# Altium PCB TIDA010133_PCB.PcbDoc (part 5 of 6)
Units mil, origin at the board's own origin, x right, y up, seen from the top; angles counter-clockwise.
Board outline 4100 x 6400 mil, 8 copper layers (Top Layer, Ground 1, Signal 1, Power 1, Ground 2, Signal 2, Power 2, Bottom Layer), stack 60.4 mil thick; 587 components, 322 nets, 1661 pads, 859 vias.
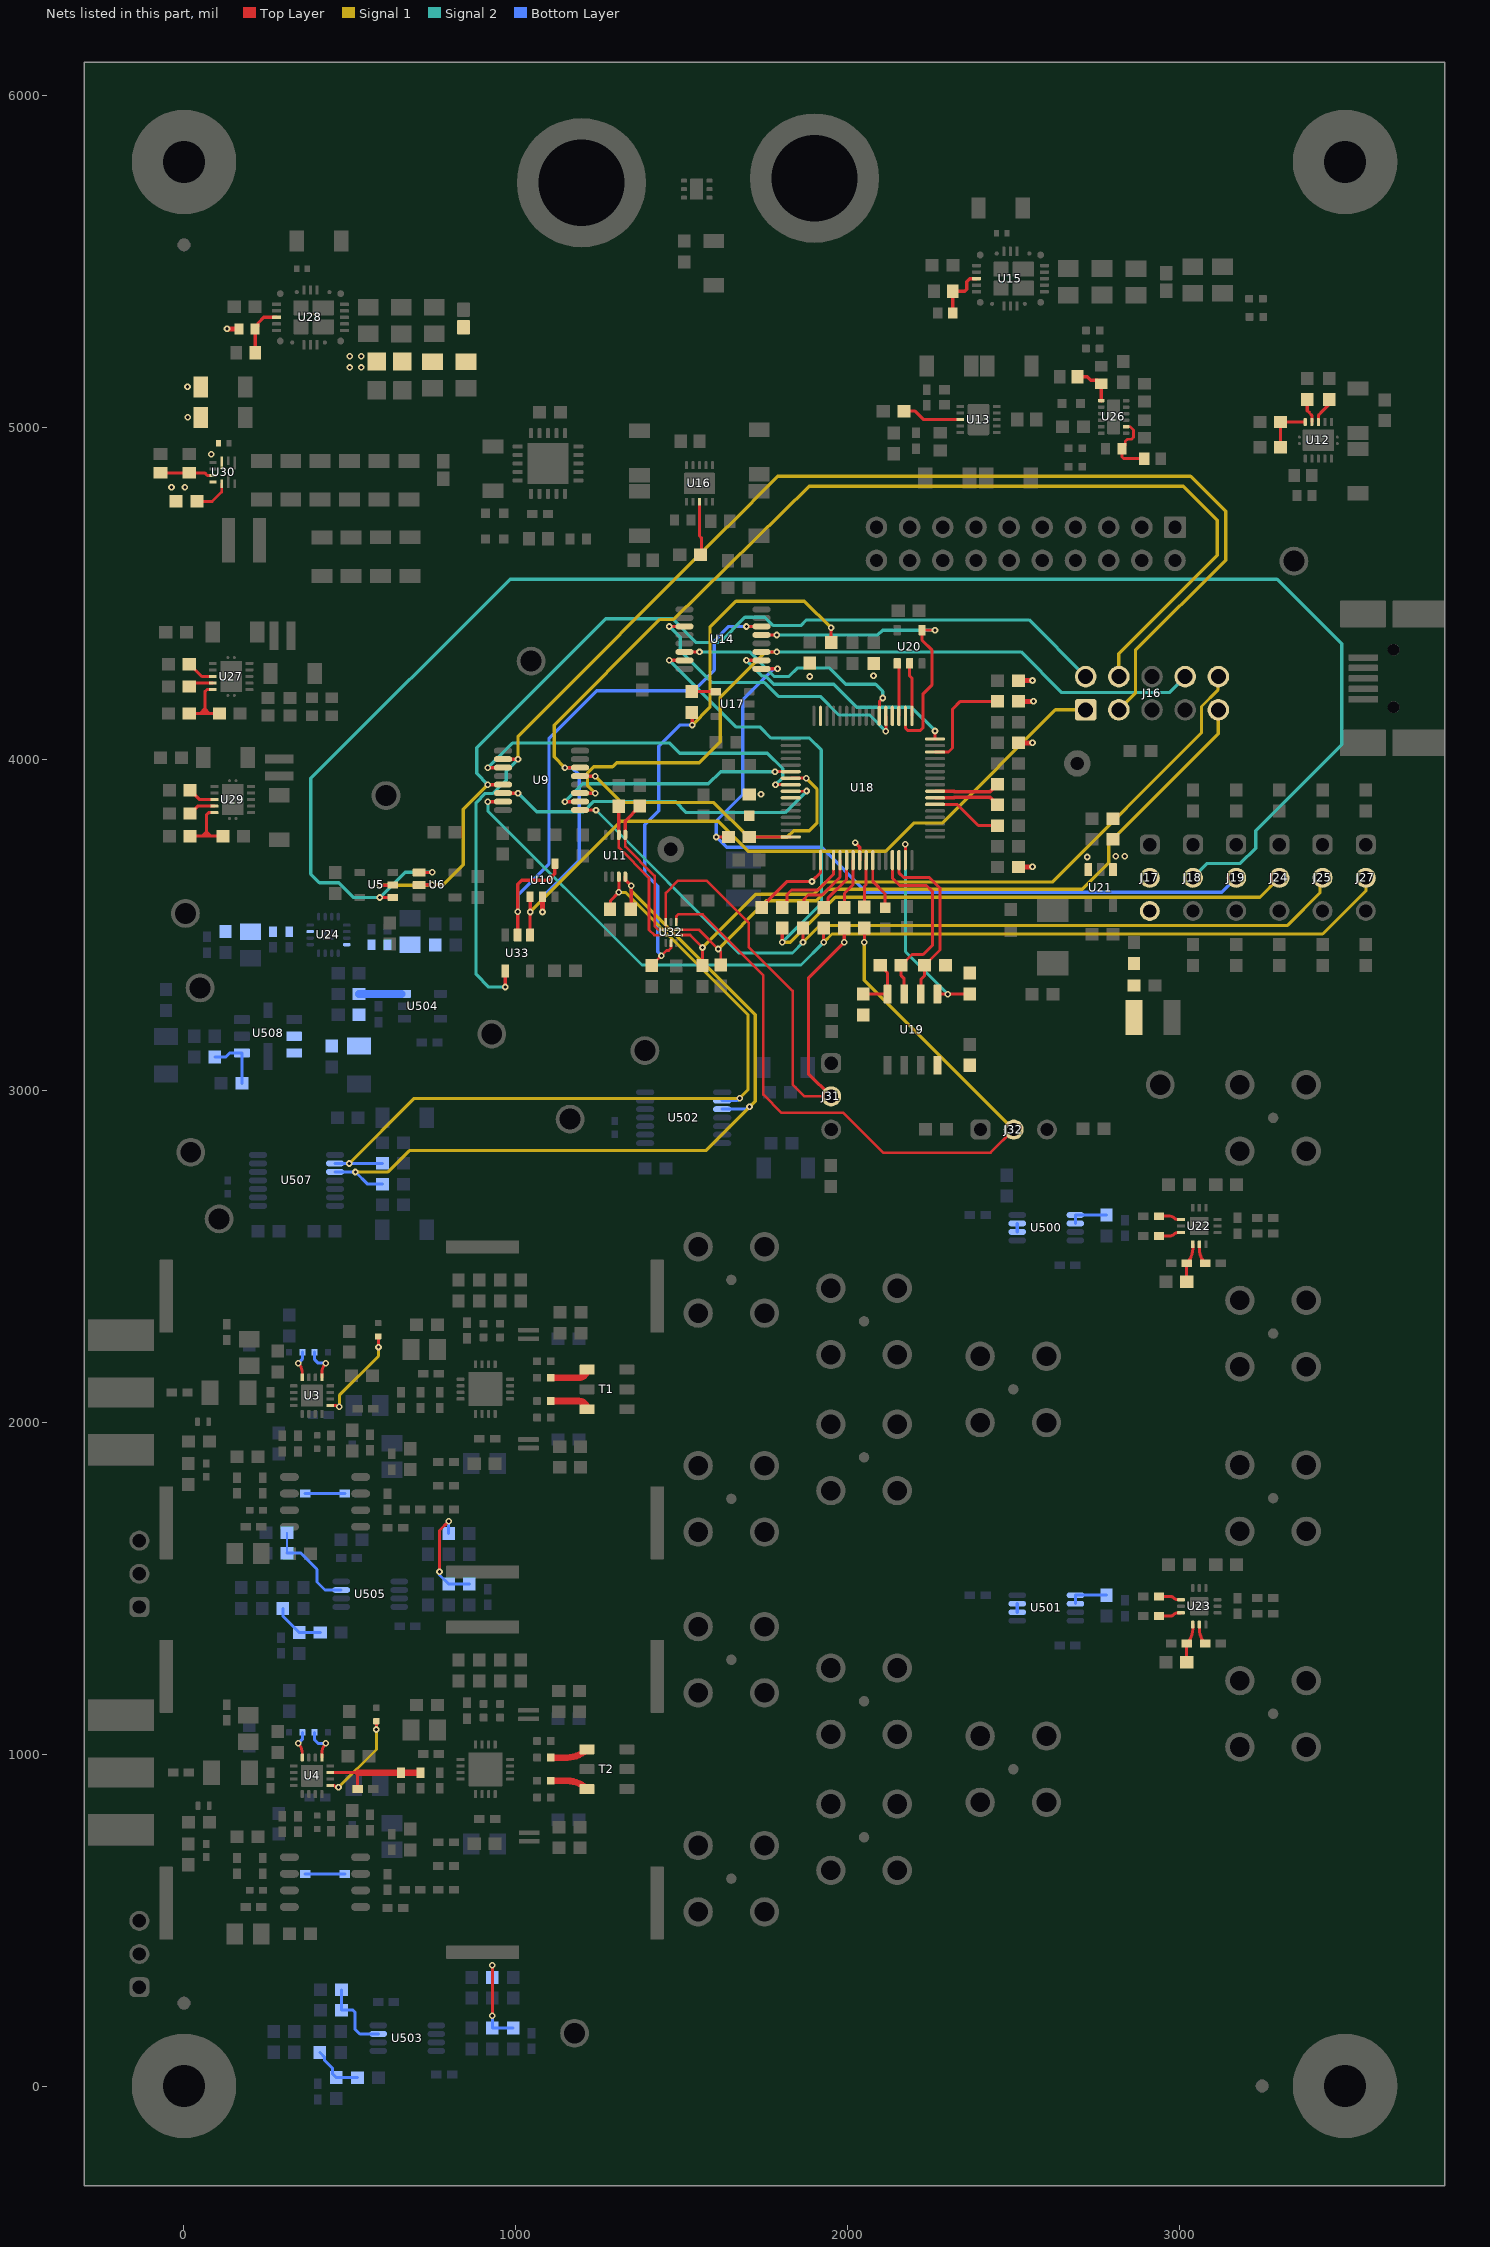
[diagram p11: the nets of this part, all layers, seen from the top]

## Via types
v1: diameter 20, hole 10, Top Layer to Bottom Layer, tented top, 776 vias
v2: diameter 19.68, hole 7.87, Top Layer to Bottom Layer, tented bottom, 82 vias
v3: diameter 19.68, hole 7.87, Top Layer to Bottom Layer, 1 vias

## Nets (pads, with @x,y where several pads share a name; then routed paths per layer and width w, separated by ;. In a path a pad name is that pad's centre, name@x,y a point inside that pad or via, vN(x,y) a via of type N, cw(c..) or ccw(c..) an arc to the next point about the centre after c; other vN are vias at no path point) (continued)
NetR66_1: R66.1 R107.2 R128.2 U32.4 | length 1715.4
  Top Layer w8: R66.1@1410.08,3378.51 v1(1439.23,3407.66) 1454.69,3423.13 1460.81,3423.13 1468.15,3430.47 U32.4@1468.15,3439.13
  Top Layer w10: R66.1@1410.08,3377.53 R66.1@1410.08,3378.51 ; R107.2@1531.18,4140.15 1531.7,4139.63 v1(1531.7,4102.57) ; R128.2@1950.64,4352.16 v1(1950.64,4395.97)
  Signal 1 w10: v1(1531.7,4102.57) 1585.53,4156.41 1585.53,4397.81 1663.84,4476.12 1870.49,4476.12 v1(1950.64,4395.97)
  Bottom Layer w10: v1(1439.23,3407.66) 1428.17,3418.72 1428.17,3617.06 1389.34,3655.89 1389.34,3802.46 1431.41,3844.53 1431.41,4039.3 1494.68,4102.57 v1(1531.7,4102.57)
NetR68_2: R68.2 U12.3 | length 81.7
  Top Layer w9.29: U12.3@3419.63,5016.08 3419.63,5036.41 3426.67,5043.45
  Top Layer w10: 3426.67,5043.45 3453,5069.78 R68.2@3453,5083.98
NetR69_2: R69.2 U12.4 | length 73.7
  Top Layer w9.29: 3392.91,5043.45 3399.95,5036.41 U12.4@3399.95,5016.08
  Top Layer w10: R69.2@3386,5083.98 3386,5050.36 3392.91,5043.45
NetR71_2: R71.2 R76.2 U12.5 | length 150.3
  Top Layer w9: R71.2@3306,4940 R76.2@3306,5016.08 U12.5@3380.26,5016.08
NetR80_1: R80.1 R82.2 U15.22 | length 165.9
  Top Layer w9.84: R82.2@2317.64,5410 2354.04,5410 2359.8,5415.77 2359.8,5439.15 2368.91,5448.25 U15.22@2388.98,5448.25
  Top Layer w10: R80.1@2317.64,5345 R82.2@2317.64,5410
NetR81_1: R81.1 U18.57 | length 143.6
  Top Layer w9: R81.1@2051.26,3554.04 2051.26,3616.75 2056.57,3622.06 U18.57@2056.57,3695.4
NetR90_1: R90.1 R91.2 U26.2 | length 198.5
  Top Layer w8: U26.2@2840.07,5001.78 2852.76,5001.78 2862.42,4992.12 2862.42,4970.42 2856.01,4964.01 2843.47,4964.01 2837.06,4957.6 2837.06,4944.94 R90.1@2827.65,4935.53 2827.65,4911.26 2832.91,4906 R91.2@2895,4906
NetR97_1: R97.1 U13.8 | length 179.5
  Top Layer w9.45: R97.1@2171,5049 2204.19,5049 2229.75,5023.44 U13.8@2339.94,5023.44
NetR98_1: R98.1 R99.2 U26.7 | length 130.8
  Top Layer w9.84: R98.1@2693.48,5152.29 2722.56,5152.29 2733.17,5141.68 2754.36,5141.68 R99.2@2765.19,5130.85 U26.7@2765.19,5080.59
NetR102_2: R102.2 U27.3 | length 86.1
  Top Layer w9.45: R102.2@16.28,4286.54 53.82,4249 U27.3@86.88,4249
NetR104_2: R104.2 U27.4 | length 73
  Top Layer w9.45: R104.2@18.33,4218.63 29.01,4229.31 U27.4@86.88,4229.31
NetR107_1: R107.1 U17.4 | length 72.4
  Top Layer w9: R107.1@1531.18,4203.14 U17.4@1603.62,4203.14
NetR109_2: R109.2 R112.2 U27.5 | length 223.2
  Top Layer w9.45: R109.2@15.74,4137.42 62.84,4137.42 ; 48.68,4137.42 62.84,4151.58 77,4137.42 ; U27.5@86.88,4209.63 69.36,4209.63 62.84,4203.11 62.84,4137.42 ; R112.2@106.41,4137.42 62.84,4137.42
NetR111_2: R111.2 U16.8 | length 162.6
  Top Layer w9.45: U16.8@1554,4775.88 1554,4672.71 1560.45,4666.26 R111.2@1560.45,4616
NetR115_1: R115.1 U18.48 | length 125.2
  Top Layer w9: R115.1@1704.02,3765.28 U18.48@1829.21,3765.28
NetR119_2: R119.2 T1.4 | length 120.6
  Top Layer w20: R119.2@1108.62,2065 1190.16,2065 cw(c1190.16,2040.16) T1.4@1215,2040.16
NetR120_2: R120.2 T1.6 | length 120.6
  Top Layer w20: R120.2@1108.62,2135 1190.16,2135 ccw(c1190.16,2159.84) T1.6@1215,2159.84
NetR123_2: R123.2 T2.4 | length 113
  Top Layer w20: R123.2@1108.62,920 1154.99,920 cw(c1154.99,835.18) T2.4@1214.96,895.16
NetR124_2: R124.2 T2.6 | length 113
  Top Layer w20: R124.2@1108.62,990 1154.99,990 ccw(c1154.99,1074.82) T2.6@1214.96,1014.84
NetR126_1: R126.1 U18.52 | length 257.8
  Top Layer w9: R126.1@1803.55,3558.72 R126.1@1803.55,3553.3 1817.75,3567.5 1817.75,3591.42 1831.47,3605.14 1910.45,3605.14 1958.15,3652.84 U18.52@1958.15,3695.4
NetR127_1: R127.1 U18.53 | length 213.4
  Top Layer w9: R127.1@1865.95,3553.3 1868.93,3556.28 1868.93,3577.71 1881.35,3590.14 1923.88,3590.14 1977.83,3644.09 U18.53@1977.83,3695.4
NetR129_1: R129.1 U18.54 | length 170.8
  Top Layer w9: R129.1@1928.35,3553.3 1940.75,3565.7 1940.75,3580.38 1997.52,3637.15 U18.54@1997.52,3695.4
NetR131_1: R131.1 R133.1 U19.4 | length 169.5
  Top Layer w9: R131.1@2047.19,3291.61 U19.4@2121.09,3291.61 2121.09,3355.8 R133.1@2098.84,3378.05
NetR132_1: R132.1 U18.55 | length 153.1
  Top Layer w9: R132.1@1990.75,3553.3 1990.75,3595.28 2017.2,3621.73 U18.55@2017.2,3695.4
NetR133_2: R133.2 U18.61 U19.3 | length 564.5
  Top Layer w9: U18.61@2135.31,3695.4 2135.31,3641.39 2157.42,3619.29 2238.02,3619.29 2257.08,3600.23 2257.08,3439.48 2228.48,3410.89 2194.68,3410.89 R133.2@2161.84,3378.05 2161.84,3347.27 2171.09,3338.02 U19.3@2171.09,3291.61
NetR135_1: R135.1 U18.62 U19.2 | length 524.1
  Top Layer w9: U18.62@2155,3695.4 2155,3657.78 2169.19,3643.59 2246.12,3643.59 2278.82,3610.89 2278.82,3424.6 R135.1@2232.27,3378.05 2232.27,3346.83 2221.09,3335.65 U19.2@2221.09,3291.61
NetR136_1: R136.1 U18.63 U19.1 | length 650.1
  Top Layer w9: U18.63@2174.68,3695.4 v1(2174.68,3743.33) ; U19.1@2271.09,3291.61 v1(2302.58,3291.61) R136.1@2368.57,3291.61
  Signal 2 w9: v1(2174.68,3743.33) 2174.68,3419.5 v1(2302.58,3291.61)
NetR137_2: R137.2 U18.8 | length 198.1
  Top Layer w9.84: U18.8@2264.25,3903.08 2301.95,3903.08
  Top Layer w11: 2301.95,3903.08 2321.53,3903.08 2322.88,3901.74 2429.73,3901.74 R137.2@2452.43,3924.44
NetR138_2: R138.2 U18.7 | length 198.1
  Top Layer w9.84: U18.7@2264.25,3883.39 2301.95,3883.39
  Top Layer w11: 2301.95,3883.39 2321.53,3883.39 2322.88,3884.74 2429.73,3884.74 R138.2@2452.43,3862.03
NetR139_1: R139.1 U18.6 | length 214.7
  Top Layer w9: U18.6@2264.25,3863.71 2330.55,3863.71 2394.63,3799.63 R139.1@2452.43,3799.63
NetR140_2: R140.2 U18.14 | length 320.1
  Top Layer w9: U18.14@2264.25,4021.19 2304.44,4021.19 2316.43,4033.18 2316.43,4150.35 2340.13,4174.05 R140.2@2452.43,4174.05
NetR143_2: R143.2 U22.6 | length 69
  Top Layer w9: R143.2@2939.24,2562.74 2972.16,2562.74 ccw(c2972.16,2580.11) 2984.44,2567.83 cw(c2996.3,2555.97) 2996.3,2572.74 U22.6@3005.54,2572.74
NetR144_2: R144.2 U22.4 | length 69
  Top Layer w9: R144.2@2939.24,2622.11 2972.16,2622.11 cw(c2972.16,2604.75) 2984.44,2617.03 ccw(c2996.3,2628.89) 2996.3,2612.11 U22.4@3005.54,2612.11
NetR145_2: R145.2 U23.6 | length 69
  Top Layer w9: R145.2@2939.24,1416.49 2972.16,1416.49 ccw(c2972.16,1433.85) 2984.44,1421.57 cw(c2996.3,1409.71) 2996.3,1426.49 U23.6@3005.55,1426.49
NetR146_2: R146.2 U23.4 | length 69
  Top Layer w9: R146.2@2939.24,1475.86 2972.16,1475.86 cw(c2972.16,1458.49) 2984.44,1470.77 ccw(c2996.3,1482.63) 2996.3,1465.86 U23.4@3005.54,1465.86
NetR147_2: R147.2 R149.2 U22.7 | length 118.3
  Top Layer w9: R147.2@3022.77,2423.85 R149.2@3022.77,2480.19 ccw(c2978.8,2524.16) 3040.98,2524.16 U22.7@3040.98,2537.31
NetR148_2: R148.2 R150.2 U23.7 | length 118.3
  Top Layer w9: R148.2@3022.77,1277.59 R150.2@3022.77,1333.94 ccw(c2978.8,1377.91) 3040.98,1377.91 U23.7@3040.98,1391.05
NetR154_1: R154.1 U22.8 | length 61.9
  Top Layer w9: U22.8@3060.66,2537.31 3060.66,2523.66 ccw(c3122.13,2523.66) R154.1@3078.67,2480.19
NetR155_1: R155.1 U23.8 | length 61.9
  Top Layer w9: U23.8@3060.66,1391.05 3060.66,1377.4 ccw(c3122.13,1377.4) R155.1@3078.67,1333.94
NetR168_2: R168.2 U29.3 | length 85
  Top Layer w9.45: R168.2@18.68,3906.4 47.07,3878 U29.3@91.88,3878
NetR169_1: R169.1 R171.2 U28.22 | length 156
  Top Layer w9.84: R171.2@214.5,5225 R169.1@214.5,5297 223.35,5305.86 223.35,5314.72 240.39,5331.75 U28.22@278.94,5331.75
NetR170_2: R170.2 U29.4 | length 82.4
  Top Layer w9.45: R170.2@18.68,3836 40.99,3858.31 U29.4@91.88,3858.31
NetR173_1: R173.1 U30.1 | length 111.3
  Top Layer w7.87: R173.1@39.14,4776.71 85.03,4776.71 113.67,4805.35 U30.1@113.67,4830.24
NetR174_2: R174.2 R176.2 U29.5 | length 227.1
  Top Layer w9.45: R174.2@18.68,3768 67.84,3768 ; 54.43,3768 67.84,3781.4 81.24,3768 ; U29.5@91.88,3838.63 74.36,3838.63 67.84,3832.11 67.84,3768 ; R176.2@117,3768 67.84,3768
NetR175_2: R175.2 R178.2 U30.9 | length 161.3
  Top Layer w9.36: R175.2@-70.89,4862.91 R178.2@16,4862.91 62.3,4862.91 70.36,4854.85 U30.9@87.09,4854.85
NetR180_1: R180.1 U3.9 | length 291
  Top Layer w9: U3.9@441.35,2051.5 460.06,2051.5 464.31,2047.25 v1(468.37,2047.25) ; R180.1@585,2260 586.37,2258.63 v1(586.37,2227.52)
  Signal 1 w9: v1(468.37,2047.25) 468.37,2082.01 586.37,2200 v1(586.37,2227.52)
NetR181_1: R181.1 U4.9 | length 271.7
  Top Layer w9: U4.9@441.35,905.25 453.84,905.25 458.7,900.38 v1(465.76,900.38) ; v1(580,1074.54) R181.1@580,1098.35
  Signal 1 w9: v1(465.76,900.38) 580,1014.62 v1(580,1074.54)
NetR500_1: R500.1 U500.1 U500.2 | length 119.5
  Bottom Layer w9: U500.2@2687.14,2600.11 U500.1@2687.14,2625.7 R500.1@2781.05,2625.7
NetR501_1: R501.1 U501.1 U501.2 | length 119.5
  Bottom Layer w9: U501.2@2687.13,1453.86 U501.1@2687.13,1479.45 R501.1@2781.04,1479.45
NetR502_1: R502.1 R503.2 U505.3 | length 293.4
  Bottom Layer w6: R502.1@309.98,1606.22 309.98,1667.11 R503.2@310.19,1667.32
  Bottom Layer w9: R502.1@309.98,1606.22 352.35,1606.22 401.18,1557.39 401.18,1519.05 424.96,1495.27 U505.3@473.81,1495.27
NetR504_1: R504.1 R505.2 U503.3 | length 233.1
  Bottom Layer w9: R505.2@475.07,290.04 475.07,256.95 474.15,256.02 R504.1@474.15,228.4 509.58,228.4 514.86,223.13 514.86,171.94 529.84,156.96 U503.3@585.63,156.96
NetR518_1: R518.1 R519.2 R520.2 | length 288.7
  Top Layer w9: v1(929.57,211.54) v1(929.57,364.38)
  Bottom Layer w9: v1(929.57,211.54) R519.2@929.57,174.85 R518.1@992.1,174.85 ; R520.2@929.57,327.69 v1(929.57,364.38)
NetR523_1: R523.1 R524.2 R525.2 | length 310.4
  Top Layer w9: v1(770.3,1550.52) 770.3,1674.68 v1(797.74,1702.12)
  Bottom Layer w9: v1(770.3,1550.52) 770.3,1540.6 R524.2@797.74,1513.16 R523.1@860.28,1513.16 ; R525.2@797.74,1666 v1(797.74,1702.12)
NetR529_2: R529.2 R535.1 R538.2 | length 160.4
  Bottom Layer w9: R538.2@409.65,101.08 423.86,86.88 423.86,77.53 448.26,53.12 448.26,36.46 R535.1@459.51,25.21 R529.2@523.43,25.21
NetR530_1: R530.1 R540.2 | length 120.1
  Bottom Layer w9: R540.2@365.05,1785.8 R530.1@485.13,1785.8
NetR531_1: R531.1 R539.2 | length 120.1
  Bottom Layer w9: R539.2@365.05,639.55 R531.1@485.13,639.55
NetR533_1: R533.1 U504.3 | length 127.8
  Bottom Layer w23.62: R533.1@528.03,3291.96 U504.3@655.88,3291.96
NetR534_2: R534.2 R541.1 R547.2 | length 156.1
  Bottom Layer w9: R547.2@297.83,1439.38 297.83,1416.8 R541.1@347.43,1367.21 R534.2@410.81,1367.21
NetR536_1: R536.1 U3.13 | length 106.4
  Top Layer w9: U3.13@415.53,2136.37 415.53,2150.06 cw(c456.58,2150.06) v1(427.55,2179.09)
  Bottom Layer w9: R536.1@393.98,2212.12 393.98,2189.51 404.4,2179.09 v1(427.55,2179.09)
NetR537_1: R537.1 U4.13 | length 106.4
  Top Layer w9: U4.13@415.53,990.12 415.53,1003.8 cw(c456.58,1003.8) v1(427.56,1032.83)
  Bottom Layer w9: R537.1@393.98,1065.87 393.98,1043.26 404.4,1032.83 v1(427.56,1032.83)
NetR543_1: R543.1 U3.16 | length 84
  Top Layer w9: v1(344.45,2179.09) cw(c315.42,2150.06) 356.48,2150.06 U3.16@356.48,2136.37
  Bottom Layer w9: v1(344.45,2179.09) 356.57,2191.2 R543.1@356.57,2212.12
NetR544_1: R544.1 U4.16 | length 84
  Top Layer w9: v1(344.45,1032.83) cw(c315.42,1003.8) 356.48,1003.8 U4.16@356.48,990.12
  Bottom Layer w9: v1(344.45,1032.83) 356.57,1044.95 R544.1@356.57,1065.87
NetR553_2: R553.2 R556.1 U508.1 | length 178.7
  Bottom Layer w9: R556.1@93.15,3101.5 125.43,3101.5 138.42,3114.49 U508.1@174.6,3114.49 R553.2@174.6,3022.59
NetU9_2: U9.2 U18.38 | length 763.8
  Top Layer w9: v1(1781.7,3962.13) U18.38@1829.21,3962.13
  Top Layer w10: v1(1148.34,3871.86) U9.2@1193.85,3871.86
  Signal 2 w10: v1(1148.34,3871.86) 1201.92,3925.44 1581.1,3925.44 1617.79,3962.13 v1(1781.7,3962.13)
NetU9_5: U9.5 U18.39 | length 1003
  Top Layer w9: U18.39@1829.21,3942.45 v1(1875.47,3942.45)
  Top Layer w10: U9.5@1193.85,3948.63 v1(1239.35,3948.63)
  Signal 1 w10: v1(1239.35,3948.63) 1319.05,3868.93 1597.41,3868.93 1701.06,3765.28 1819.07,3765.28 1837.44,3783.65 1885.42,3783.65 1907.94,3806.17 1907.94,3909.98 v1(1875.47,3942.45)
NetU9_11: U9.11 U18.40 | length 1100.8
  Top Layer w9: v1(1782.95,3922.76) U18.40@1829.21,3922.76
  Top Layer w10: v1(916.06,3974.22) U9.11@961.56,3974.22
  Signal 2 w10: v1(916.06,3974.22) 990.24,4048.4 1463.97,4048.4 1494.5,4017.87 1758.49,4017.87 1804.7,3971.66 1804.7,3944.51 v1(1782.95,3922.76)
NetU9_14: U9.14 U18.41 | length 1039
  Top Layer w9: U18.41@1829.21,3903.08 v1@1876.2,3903.08
  Top Layer w10: U9.14@961.56,3897.45 v1(1007.07,3897.45)
  Signal 2 w10: v1(1007.07,3897.45) 1063.07,3841.45 1204.47,3841.45 1235.32,3872.3 1480.46,3872.3 1513.94,3838.81 1811.94,3838.81 v1(1876.81,3903.69)
NetU14_2: U14.2 U18.16 | length 726.6
  Top Layer w9: U18.16@2264.25,4060.56 v1@2264.25,4084.96
  Top Layer w10: v1(1695.46,4297.54) U14.2@1740.97,4297.54
  Signal 2 w10: v1(1695.46,4297.54) 1742.73,4250.27 1753.18,4250.27 1778.27,4225.18 1958.55,4225.18 2027.73,4155.99 2192.88,4155.99 v1(2264.08,4084.79)
NetU14_5: U14.5 U18.18 U20.4 | length 983.2
  Top Layer w9: U18.18@2174.68,4130.44 2174.68,4093.34 2182.49,4085.54 2218.43,4085.54 2228.4,4095.52 2228.4,4197.39 2255.44,4224.43 2255.44,4328.08 2224.88,4358.64 U20.4@2224.88,4388.78 v1(2263.8,4388.78)
  Top Layer w10: U14.5@1740.97,4374.31 v1(1786.47,4374.31)
  Signal 2 w10: v1(1786.47,4374.31) 2070.95,4374.31 2071.07,4374.18 2088.47,4374.18 2088.59,4374.31 2091.42,4374.31 2105.89,4388.78 v1(2263.8,4388.78)
NetU14_11: U14.11 U18.21 | length 900
  Top Layer w9: v1@2115.63,4082.93 v1(2115.63,4084.18) U18.21@2115.63,4130.44
  Top Layer w10: v1(1463.18,4399.9) U14.11@1508.69,4399.9
  Signal 2 w10: v1(1463.18,4399.9) 1495.71,4367.37 1495.71,4326.79 1591.7,4230.79 1750.03,4230.79 1792.03,4188.79 1918.66,4188.79 1974.5,4132.95 2066.86,4132.95 v1(2115.63,4084.18)
NetU14_14: U14.14 U18.22 | length 746
  Top Layer w9: U18.22@2095.94,4130.44 2095.94,4173.74 v1(2106.42,4184.22)
  Top Layer w10: U14.14@1508.69,4323.13 v1(1554.19,4323.13)
  Signal 2 w10: v1(1554.19,4323.13) 1705.35,4323.13 1779.47,4249 1822.89,4249 1848.26,4274.37 1946.13,4274.37 1994.87,4225.64 2084.8,4225.64 2106.42,4204.02 v1(2106.42,4184.22)
NetU18_17: U18.17 U20.2 | length 160.8
  Top Layer w9: U20.2@2187.48,4288.39 2187.48,4250.62 2194.37,4243.73 U18.17@2194.37,4130.44
NetU18_19: U18.19 U20.1 | length 160
  Top Layer w9: U20.1@2150.08,4288.39 2155,4283.46 U18.19@2155,4130.44
NetU500_6: U500.6 U500.7 | length 25.6
  Bottom Layer w10: U500.6@2511.94,2574.52 U500.7@2511.94,2600.11
NetU501_6: U501.6 U501.7 | length 25.6
  Bottom Layer w10: U501.6@2511.94,1428.27 U501.7@2511.94,1453.86
OUT_2: C32.1 R27.2 R37.1 U4.11 | length 320.6
  Top Layer w9: U4.11@441.12,944.84 523.5,944.84 R27.2@523.5,895.59
  Top Layer w20: 523.5,944.84 R37.1@653.88,944.84 C32.1@712.5,944.84
PRG_STS: D6.2 U18.58 | length 159.5
  Top Layer w9: U18.58@2076.26,3695.4 2076.26,3631.73 2076.35,3631.64 2113.77,3593.63 D6.2@2113.77,3551.27
SMB_CLK: R95.1 R528.1 U11.4 U502.10 U507.10 | length 2447
  Top Layer w10: U11.4@1330.44,3645.46 1330.44,3635.62 v1(1348.13,3617.93) 1348.13,3548.86 R95.1@1346.59,3547.31
  Signal 1 w10: v1(516.75,2755.5) 615.16,2755.5 679.57,2819.91 1572.95,2819.91 v1(1704.86,2951.82) 1722.03,2968.99 1722.03,3229.27 1348.43,3602.86 1348.43,3617.63 v1(1348.13,3617.93)
  Bottom Layer w9: U507.10@455.4,2755.5 v1(516.75,2755.5) 553.56,2718.69 R528.1@598.11,2718.69 ; U502.10@1622.39,2944.66 1697.7,2944.66 v1(1704.86,2951.82)
SMB_CLK_1: R96.1 U11.5 U32.1 | length 463.4
  Top Layer w8: U11.5@1330.44,3771.44 1330.44,3736.23 1419.05,3647.61 1419.05,3496.85 1430.6,3485.31 U32.1@1446.5,3485.31
  Top Layer w10: U11.5@1330.44,3771.44 1330.44,3813.4 1374.31,3857.27 R96.1@1374.31,3858.25 R96.1@1363.82,3847.76
SMB_DAT: R93.1 R527.1 U11.3 U502.9 U507.9 | length 2370
  Top Layer w9: R93.1@1284.19,3547.31 1285.55,3548.68 1285.55,3573.19 v1(1310.76,3598.39) U11.3@1310.76,3645.46
  Signal 1 w9: v1(497.8,2781.09) 694.12,2977.41 v1(1674.86,2977.41) 1699.62,3002.17 1699.62,3021.52 1699.69,3021.59 1699.69,3038.57 1699.62,3038.64 1699.62,3229.75 1330.98,3598.39 v1(1310.76,3598.39)
  Bottom Layer w9: U507.9@455.4,2781.09 v1(497.8,2781.09) R527.1@598.18,2781.09 ; U502.9@1622.39,2970.25 1667.7,2970.25 v1(1674.86,2977.41)
SMB_DAT_1: R94.1 U11.6 U32.2 | length 461.3
  Top Layer w8: U11.6@1310.76,3771.44 1310.76,3733.28 1401.87,3642.17 1401.87,3485.21 1417.77,3469.31 U32.2@1446.25,3469.31
  Top Layer w10: U11.6@1310.76,3771.44 R94.1@1310.76,3857.8
TPS62913_IBB_IN: C113.2 C115.1 C116.1 C145.1 C146.1 FB2.2 R113.1 R114.1 R169.2 R173.2 U30.6 U30.10 | length 35.7
  Top Layer w15: v1(129.57,5297) R169.2@165.28,5297
  other v1: -37.48,4819.45 2.78,4819.39 82.1,4919.36 11.01,5030.35 10.59,5122.02 499.67,5180.73 534.67,5180.73 499.67,5214.48 534.67,5214.48
U2A_DAC_EN: J27.2 R129.2 U9.15 | length 3087.6
  Top Layer w9: v1(1928.35,3447.68) R129.2@1928.35,3490.31
  Top Layer w10: v1(916.06,3871.86) U9.15@961.56,3871.86
  Signal 1 w9: v1(1928.35,3447.68) 1953.34,3472.67 3432.7,3472.67 3562.51,3602.48 J27.2@3562.51,3642.21
  Signal 2 w9: v1(916.06,3871.86) 916.06,3843.66 1380.73,3378.99 1859.66,3378.99 v1(1928.35,3447.68)
U2A_DAC_SEL: J25.2 R127.2 U9.1 | length 2576.5
  Top Layer w9: v1(1865.95,3447.68) R127.2@1865.95,3490.31
  Top Layer w10: U9.1@1193.85,3846.27 v1(1241.88,3846.32)
  Signal 1 w9: v1(1865.95,3447.68) 1917.27,3499 3327.01,3499 3424.04,3596.03 3424.04,3633.97 J25.2@3432.28,3642.21
  Signal 2 w9: v1(1241.88,3846.32) 1673.09,3415.11 1834.04,3414.92 1834.04,3415.77 v1(1865.95,3447.68)
U2A_I2C_CLK: J16.9 R55.1 U32.7 | length 2079.1
  Top Layer w8: U32.7@1490.06,3485.56 1552.23,3485.56 v1(1610.27,3427.52) 1618.51,3419.31 R55.1@1618.56,3379.53
  Top Layer w15: R55.1@1618.56,3379.53 R55.1@1618.7,3379.67
  Signal 1 w10: v1(1610.27,3427.52) 1755.47,3572.72 1906.31,3572.72 1941.53,3607.94 2708.44,3607.94 2787.73,3687.22 2787.73,3746.43 3118.16,4076.86 J16.9@3118.16,4148.56
U2A_I2C_DAT: J16.10 R67.1 U32.6 | length 2105.9
  Top Layer w8: U32.6@1489.81,3469.56 1525.71,3469.56 v1(1563.09,3432.18) R67.1@1563.09,3377.9
  Signal 1 w9: 1934.3,3628.99 2617.42,3628.99 3067.58,4079.15 3067.58,4158.76 3116.67,4207.85 3116.67,4247.07 J16.10@3118.16,4248.56
  Signal 1 w10: v1(1563.09,3432.18) 1723.52,3592.6 1897.92,3592.6 1934.3,3628.99
U2A_I2C_EN: J32.2 R81.2 U32.8 | length 2368.6
  Top Layer w8: U32.8@1483.9,3508.93 1483.9,3526.16 1489.76,3532.01 1562.96,3532.01 1746.7,3348.28 1746.7,2988.23 1801.4,2933.53 1987.51,2933.53 2107.57,2813.47 2431.53,2813.47 J32.2@2501.29,2883.22
  Top Layer w10: v1@2051.26,3448.14 R81.2@2051.26,3491.05
  Signal 1 w10: v1(2051.12,3447.99) 2051.12,3333.4 J32.2@2501.29,2883.22
U2A_I2C_SEL: J31.2 R132.2 U32.10 | length 1658.8
  Top Layer w8: U32.10@1452.15,3509.18 1452.15,3596.12 1452.59,3596.56 1488.98,3633.38 1575.8,3633.38 1702.18,3506.99 1702.18,3433.46 1834.93,3300.72 1834.93,3019.31 1870.88,2983.36 J31.2@1951.03,2983.36
  Top Layer w10: J31.2@1951.03,2983.36 1882.44,3051.95 1882.44,3339.37 v1(1990.75,3447.68) R132.2@1990.75,3490.31
U2A_LMH6518_SDIO: U10.4 U14.6 U33.2 | length 1703.2
  Top Layer w10: U33.2@1005.78,3469.47 1005.78,3622.68 1018.19,3635.08 1099.18,3635.08 1118.13,3654.03 U10.4@1118.13,3685.16 ; v1(1695.46,4399.9) U14.6@1740.97,4399.9
  Bottom Layer w10: v1(1005.77,3539.41) 1005.77,3589.4 1100.1,3683.73 1100.1,4061.52 1244.63,4206.05 1536.29,4206.05 1598.68,4268.44 1598.68,4356 1642.58,4399.9 v1(1695.46,4399.9)
U2A_LMH_CSSEL: J18.2 U5.1 U6.1 | length 5179.5
  Top Layer w10: v1@590.66,3582.76 U5.1@629.7,3582.76 ; U6.1@708.84,3658.31 v1@747.88,3658.31
  Signal 2 w10: v1(748.01,3658.44) 666.34,3658.44 v1(590.53,3582.63) 511,3582.63 466.04,3627.58 408.24,3627.58 382.32,3653.51 382.32,3941.85 982.84,4542.37 3295.09,4542.37 3489.78,4347.68 3489.78,4043.83 3230.59,3784.63 3230.59,3731.2 3184.72,3685.33 3084.69,3685.33 J18.2@3041.57,3642.21
U2A_LMH_EN: J24.2 R126.2 U14.15 | length 2866.1
  Top Layer w9.5: v1(1803.55,3447.68) R126.2@1803.55,3490.31
  Top Layer w10: v1(1463.18,4297.54) U14.15@1508.69,4297.54
  Signal 1 w9.5: v1(1803.55,3447.68) 1827.67,3447.68 1963.64,3583.66 3243.48,3583.66 J24.2@3302.04,3642.21
  Signal 2 w9.5: v1(1463.18,4297.54) 1663.55,4097.16 1735.77,4097.16 1769.31,4063.62 1885.35,4063.62 1921.1,4027.88 1921.99,3566.13 v1(1803.55,3447.68)
U2A_LMH_SEL: J19.2 R115.2 U14.1 | length 2329.1
  Top Layer w9: v1(1604.34,3765.28) R115.2@1641.02,3765.28
  Top Layer w10: U14.1@1740.97,4271.95 v1(1789,4272)
  Bottom Layer w10: v1(1789,4272) 1787.09,4270.09 1775.03,4270.09 1684.23,4179.29 1684.23,3893.3 1604.34,3813.4 v1(1604.34,3765.28) 1635.63,3733.99 1922.46,3733.99 2057.36,3599.1 3128.69,3599.1 J19.2@3171.8,3642.21
U2A_SDIO_SEL: J16.1 U10.1 U33.1 | length 2117.4
  Top Layer w10: U33.1@1043.18,3469.47 1043.25,3469.54 1043.25,3539.19 v1(1043.32,3539.26) U10.1@1043.32,3584.77
  Signal 1 w10: v1(1043.32,3539.26) 1316.68,3812.62 1610.07,3812.62 1700.35,3722.33 2114.86,3722.33 2199.65,3807.11 2285.58,3807.11 2627.03,4148.56 J16.1@2718.16,4148.56
U2A_SPI_CS: J16.2 U5.2 U6.2 U9.13 | length 2944.5
  Top Layer w10: v1@590.66,3620.16 U5.2@629.7,3620.16 ; U6.2@708.84,3620.9 v1@747.88,3620.9 ; v1(916.06,3923.04) U9.13@961.56,3923.04
  Signal 1 w10: v1(590.53,3620.03) 747.01,3620.03 v1(748.01,3621.03) 781.35,3621.03 841.5,3681.19 841.5,3848.49 v1(916.06,3923.04)
  Signal 2 w10: v1(916.06,3923.04) 882.2,3956.89 882.2,4034.04 1271.06,4422.9 1473.07,4422.9 1544.66,4351.31 1614.35,4351.31 1691.12,4428.08 1751.36,4428.08 1776.95,4402.49 1859.68,4402.49 1876.55,4419.36 2547.36,4419.36 J16.2@2718.16,4248.56
U2A_SPI_MISO: J16.3 U9.10 U33.4 | length 4215.5
  Top Layer w10: U9.10@961.56,3999.81 v1(1007.07,3999.81) ; v1(968.3,3312.86) v1(968.3,3312.86) 968.34,3361.16 U33.4@968.38,3361.2
  Signal 1 w10: v1(1007.07,3999.81) 1007.07,4069.45 1624.22,4686.6 1624.22,4687.35 1636.52,4699.65 1637.27,4699.65 1790.29,4852.67 3034.31,4852.67 3139.99,4746.98 3139.99,4599.85 2868.16,4328.03 2868.16,4198.56 J16.3@2818.17,4148.56
  Signal 2 w10: v1(968.3,3312.86) 918.43,3312.86 880.4,3350.89 880.4,3868.62 908.19,3896.42 931.5,3896.42 970.98,3935.9 970.98,3963.72 v1(1007.07,3999.81)
U2A_SPI_MOSI: J16.4 U9.6 U10.2 | length 3675
  Top Layer w10: v1(1148.34,3974.22) U9.6@1193.85,3974.22
  Top Layer w15: v1(1080.73,3539.26) U10.2@1080.73,3584.77
  Signal 1 w10: v1(1148.34,3974.22) 1115.89,4006.68 1115.89,4101.99 1434.79,4420.9 1476.66,4420.9 1884.54,4822.39 3012.44,4822.39 3114.85,4719.97 3114.85,4614.36 2818.17,4317.67 J16.4@2818.17,4248.56
  Bottom Layer w10: v1(1080.73,3539.26) 1080.73,3584.4 1191.13,3694.81 1191.13,3952.2 1169.11,3974.22 v1(1148.34,3974.22)
U2A_SPI_SCLK: J16.8 U9.3 U14.3 | length 2263.3
  Top Layer w10: U9.3@1193.85,3897.45 v1(1239.35,3897.45) ; U14.3@1740.97,4323.13 v1(1786.47,4323.13)
  Signal 1 w10: v1(1239.35,3897.45) 1216.35,3920.45 1216.35,3957.89 1235.27,3976.81 1291.96,3976.81 1304.27,3989.13 1553.81,3989.13 1616.76,4052.09 1616.76,4186.31 1753.58,4323.13 v1(1786.47,4323.13)
  Signal 2 w10: v1(1786.47,4323.13) 2523.45,4323.13 2645.96,4200.62 2970.22,4200.62 J16.8@3018.16,4248.56
V3P3V_DAC: C536.1 C543.1 C547.1 L509.2 U24.16
V_BUS: C85.2 C94.1 C95.2 J17.3 L22.2 R131.2 R135.2 R136.2 U19.8
VA2P5V_DACREFEXT1: C548.1 C554.1 R532.2 U508.6 U508.7
VA5V_DAC: C561.1 C565.1 C566.1 L515.2 U24.7
VBUS: C92.1 R141.2 U21.1 U21.3
  other v1: 2722.86,3705.02 2808.73,3706.77 2835.77,3706.77
VREGIN: C66.2 C81.2 C82.2 C83.2 C89.2 D5.1 J17.2 L20.2 L21.1 R140.1 U18.20 U18.31 U18.42 U18.50 U18.56 | length 486.1
  Top Layer w9.84: 1874.76,3631.18 v1(1893.02,3631.18) 1918.78,3656.94 U18.50@1918.78,3695.4 ; v1(2023.19,3748.34) 2036.89,3734.64 U18.56@2036.89,3695.4
  Top Layer w10: C81.2@1741.14,3553.3 1741.14,3554.29 1818.04,3631.18 1874.76,3631.18
  Top Layer w15: L20.2@2515.43,3674.83 v1@2557.41,3674.83 ; L21.1@2515.43,4049.24 v1@2557.41,4049.24 ; C89.2@2515.43,4236.45 v1@2557.41,4236.45 ; R140.1@2518.38,4174.05 v1@2560.36,4174.05
  other v1: 2557.91,3675.34 1739.36,3894.38 2557.91,4049.75 2560.87,4174.55 2557.91,4236.95 1886.34,4248.89 2078.5,4251.02
pads on no net: FID1.1 FID2.1 FID3.1 FID4.1 FID5.1 FID6.1 H1.1 H2.1 H15.1 H16.1 H500.0 H501.0 H502.0 H503.0 J3.1 J4.1 J7.1 J7.3 J7.5 J7.7 J7.9 J7.11 J7.13 J16.7 J26. J26.4 LBL1.0 T1.5 T2.5 U15.4 U15.19 U18.36 U18.60 U19.6 U19.7 U21.4 U24.10 U24.11 U25.7@1545.46,5700.46 U25.7@1545.46,5735.89 U28.4 U28.19 U30.5 U30.8
copper on no net:
  other v1: 1222.29,3441.84

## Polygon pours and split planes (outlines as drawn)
GND on Top Layer "Top Layer-GND" (solid, remove dead copper, pour order 52905): -311.96,6047.55 -311.96,-352.45 3788.04,-352.45 3788.04,6047.55 3784.47,6047.55
-2.5VA on Top Layer "TOP_LAYER_-2.5VA_P52868" (solid, remove dead copper, pour order 52868): 17 vertices, not listed, extent 2199.74,5057.24 2352.57,5225.98
-5VA_OPA140_1 on Top Layer "TOP_LAYER_-5VA_OPA140_1_P52878" (solid, remove dead copper, pour order 52878): 218.35,1541.31 336.48,1541.31 346.31,1551.14 346.32,1699.76 336.33,1709.74 212.07,1709.74 207.64,1705.31 207.64,1552.02
V_BUS on Top Layer "TOP_LAYER_V_BUS_P52904" (solid, remove dead copper, pour order 52904): 55 vertices, not listed, extent 2019.8,2959.22 2980.99,3601.96
+3.8V_IN_TPS7A94 on Top Layer "TOP_LAYER_+3.8V_IN_TPS7A94_P52903" (solid, remove dead copper, pour order 52903): 25 vertices, not listed, extent 3241.03,5003.5 3666.48,5440.08
+3P3VD on Top Layer "TOP_LAYER_+3P3VD_P52901" (solid, remove dead copper, pour order 52901): 17 vertices, not listed, extent 2863.76,3679.36 3617.3,4002.62
+2.5VA on Top Layer "TOP_LAYER_+2.5VA_P52900" (solid, remove dead copper, pour order 52900): 358.99,2605.56 390.84,2573.71 390.84,2478.04 361.63,2448.83 284.64,2448.83 144.17,2448.83 -1,2594 -1,2705 18.21,2724.21 185.56,2724.21 304.21,2605.56
+5VA_LMH6518_2 on Top Layer "TOP_LAYER_+5VA_LMH6518_2_P52897" (solid, remove dead copper, pour order 52897): 30 vertices, not listed, extent 693.28,1015.88 976.59,1352.01
+5VA_LMH6518_1 on Top Layer "TOP_LAYER_+5VA_LMH6518_1_P52896" (solid, remove dead copper, pour order 52896): 30 vertices, not listed, extent 693.28,2162.14 976.59,2498.27
NetC110_1 on Top Layer "TOP_LAYER_NETC110_1_P52894" (solid, remove dead copper, pour order 52894): 856.41,5432.89 866.39,5422.91 866.39,5338.2 855.23,5327.04 464.91,5327.04 456.05,5335.9 388.46,5335.9 385.56,5338.79 385.56,5384.02 396.28,5394.73 396.28,5429.15 400.02,5432.89
NetC106_1 on Top Layer "TOP_LAYER_NETC106_1_P52893" (solid, remove dead copper, pour order 52893): 2566.09,5452.4 2575,5443.5 2971.62,5443.5 2978.42,5450.3 2978.42,5507.01 2971.5,5513.92 2635.93,5513.92 2600.45,5549.4 2509.16,5549.4 2506.33,5546.57 2506.33,5511.25 2495.6,5500.52 2495.6,5455.3 2498.5,5452.4
+3P3VD on Top Layer "TOP_LAYER_+3P3VD_P52889" (solid, remove dead copper, pour order 52889): 27 vertices, not listed, extent 1352.65,4019.27 1629.55,4310.94
+5.5V_IN_TPS7A94 on Top Layer "TOP_LAYER_+5.5V_IN_TPS7A94_P52884" (solid, remove dead copper, pour order 52884): 27 vertices, not listed, extent -83.12,4182.7 112.71,4418.82
CH2_LMH6518_MVCM on Top Layer "TOP_LAYER_CH2_LMH6518_MVCM_P52882" (solid, remove dead copper, pour order 52882): 972.11,930.46 1000.42,930.46 1027.94,902.94 1027.94,854.96 1046.9,836.01 1142.41,836 1157.25,821.17 1157.24,674.15 1155.83,672.73 1084.48,672.73 1003.43,753.78 1003.43,854.19 970.22,887.4 970.22,928.57
+5.5V_IN_TPS7A94 on Top Layer "TOP_LAYER_+5.5V_IN_TPS7A94_P52880" (solid, remove dead copper, pour order 52880): 24 vertices, not listed, extent -79.19,3811.7 104.11,4041.72
-5VA_OPA140_2 on Top Layer "TOP_LAYER_-5VA_OPA140_2_P52879" (solid, remove dead copper, pour order 52879): 218.35,395.06 336.48,395.06 346.31,404.89 346.32,553.5 336.33,563.48 212.07,563.48 207.64,559.05 207.64,405.76
1P8V_USB on Top Layer "TOP_LAYER_1P8V_USB_P52877" (solid, remove dead copper, pour order 52877): 1580.03,3731.48 1585.12,3736.58 1899.27,3736.58 1903.11,3732.74 1903.11,3674.41 1898.99,3670.29 1862.4,3670.29 1651.28,3670.29 1586.29,3670.29 1580.03,3676.55
CH1_LMH6518_AVCM on Top Layer "TOP_LAYER_CH1_LMH6518_AVCM_P52874" (solid, remove dead copper, pour order 52874): 19 vertices, not listed, extent 970.22,2125.16 1157.24,2370.04
CH2_LMH6518_AVCM on Top Layer "TOP_LAYER_CH2_LMH6518_AVCM_P52873" (solid, remove dead copper, pour order 52873): 19 vertices, not listed, extent 970.22,978.91 1157.25,1223.79
CH1_LMH6518_MVCM on Top Layer "TOP_LAYER_CH1_LMH6518_MVCM_P52872" (solid, remove dead copper, pour order 52872): 19 vertices, not listed, extent 970.22,1833.47 1157.24,2076.72
+8VA_BUF802_1 on Top Layer "TOP_LAYER_+8VA_BUF802_1_P52871" (solid, remove dead copper, pour order 52871): 142.2,2194.09 87.84,2194.09 83.33,2189.58 83.33,2132.09 87.63,2127.79 272.9,2127.79 295.34,2105.35 342.01,2105.35 343.85,2107.13 343.85,2132.33 296.31,2179.87 258.03,2179.87 224.88,2213.02 161.12,2213.02
+8VA_BUF802_2 on Top Layer "TOP_LAYER_+8VA_BUF802_2_P52870" (solid, remove dead copper, pour order 52870): 142.2,1047.84 87.84,1047.84 83.33,1043.33 83.33,985.83 87.63,981.54 272.9,981.54 295.34,959.09 342.01,959.09 343.85,960.88 343.85,986.08 296.31,1033.62 258.03,1033.62 224.88,1066.76 161.12,1066.76
3P3USB on Top Layer "TOP_LAYER_3P3USB_P52869" (solid, remove dead copper, pour order 52869): 17 vertices, not listed, extent 2232.41,3918.07 2479.84,4074.56
VBUS on Top Layer "TOP_LAYER_VBUS_P52866" (solid, remove dead copper, pour order 52866): 2785.6,3649.57 2791.39,3643.78 2840.13,3643.78 2848.69,3652.35 2848.69,3880.24 2842.89,3886.03 2783.76,3886.04 2775.49,3877.77 2775.49,3780.3 2785.6,3770.19 2785.6,3719.49
NetC93_1 on Top Layer "TOP_LAYER_NETC93_1_P52865" (solid, remove dead copper, pour order 52865): 2844.2,3583.65 2837.21,3590.64 2771.78,3590.64 2768.45,3587.31 2768.45,3434.79 2776.3,3426.95 2883.21,3426.95 2886.95,3430.69 2886.95,3470.77 2844.2,3513.52
+12VA on Top Layer "TOP_LAYER_+12VA_P52864" (solid, remove dead copper, pour order 52864): 350.03,5494.3 368.75,5513.01 368.75,5614.92 364.57,5619.1 291.45,5619.1 284.43,5612.08 284.43,5461.92 317.32,5429.03 317.32,5399.49 319.33,5397.48 342.78,5397.48 346.75,5401.44 346.75,5463.56 350.03,5466.84
-3.3VA_BUF802_2 on Top Layer "TOP_LAYER_-3.3VA_BUF802_2_P52862" (solid, remove dead copper, pour order 52862): 27 vertices, not listed, extent 328.82,713.07 532.37,893.64
+5VA_OPA140_1 on Top Layer "TOP_LAYER_+5VA_OPA140_1_P52861" (solid, remove dead copper, pour order 52861): 634.47,1815.49 653.38,1796.59 721.83,1796.59 734.07,1808.83 734.07,1867.35 721.08,1880.35 612.05,1880.35 587.12,1855.43 508.88,1855.43 498.03,1844.57 498.02,1821.73 504.26,1815.49
+5VA_OPA140_2 on Top Layer "TOP_LAYER_+5VA_OPA140_2_P52860" (solid, remove dead copper, pour order 52860): 634.47,669.24 653.38,650.34 721.83,650.33 732.96,661.46 732.96,722.21 721.08,734.09 612.05,734.09 587.13,709.17 508.88,709.17 498.03,698.32 498.03,675.48 504.26,669.24
-3.3VA_BUF802_1 on Top Layer "TOP_LAYER_-3.3VA_BUF802_1_P52859" (solid, remove dead copper, pour order 52859): 27 vertices, not listed, extent 328.82,1859.32 532.37,2039.9
+3P3VD_LMH6518_2 on Top Layer "TOP_LAYER_+3P3VD_LMH6518_2_P52858" (solid, remove dead copper, pour order 52858): 935.77,894.54 942.38,894.54 987.65,849.27 987.65,680.8 972.06,665.21 923.09,665.21 917.81,670.49 917.81,817.11 938.87,838.18 938.87,856.19 932.48,862.58 932.48,891.25
+3P3VD_LMH6518_1 on Top Layer "TOP_LAYER_+3P3VD_LMH6518_1_P52857" (solid, remove dead copper, pour order 52857): 935.77,2040.79 942.38,2040.79 987.65,1995.52 987.65,1827.05 972.06,1811.46 923.09,1811.46 917.8,1816.75 917.8,1963.36 938.87,1984.43 938.87,2002.44 932.48,2008.83 932.48,2037.5
+8VA_BUF802_2 on Top Layer "TOP_LAYER_+8VA_BUF802_2_P52854" (solid, remove dead copper, pour order 52854): 17 vertices, not listed, extent 427.55,957.84 597.96,1079.9
+8VA_BUF802_1 on Top Layer "TOP_LAYER_+8VA_BUF802_1_P52853" (solid, remove dead copper, pour order 52853): 17 vertices, not listed, extent 427.55,2104.09 597.96,2226.15
VREGIN on Top Layer "TOP_LAYER_VREGIN_P52852" (solid, remove dead copper, pour order 52852): 2128.41,4100.04 2137.94,4100.04 2142.64,4104.74 2142.64,4255.29 2127.25,4270.67 2127.25,4312.07 2121.02,4318.29 2060.6,4318.29 2057.86,4315.56 2057.86,4252.58 2124.24,4186.2 2124.24,4104.2
VREGIN on Top Layer "TOP_LAYER_VREGIN_P52851" (solid, remove dead copper, pour order 52851): 19 vertices, not listed, extent 1677.91,3803.09 1859.83,3920.37
+5VA on Top Layer "TOP_LAYER_+5VA_P52850" (solid, remove dead copper, pour order 52850): 365.19,4324.22 308.09,4324.22 303.99,4328.31 303.99,4450.31 308.25,4454.57 365.57,4454.57 372.86,4447.28 372.86,4331.88
+5VA on Top Layer "TOP_LAYER_+5VA_P52849" (solid, remove dead copper, pour order 52849): 239.19,4037.77 239.19,3980.67 243.28,3976.57 365.28,3976.57 369.54,3980.83 369.54,4038.15 362.25,4045.44 246.85,4045.44
VREGIN on Top Layer "TOP_LAYER_VREGIN_P52848" (solid, remove dead copper, pour order 52848): 1913.6,4097.51 1923.14,4097.51 1927.83,4102.21 1927.83,4193.5 1912.45,4208.88 1912.45,4309.54 1906.22,4315.77 1866.84,4315.77 1862.28,4311.21 1862.28,4217.65 1909.44,4170.49 1909.44,4101.68
+5VA_TLV3605_2 on Top Layer "TOP_LAYER_+5VA_TLV3605_2_P52846" (solid, remove dead copper, pour order 52846): 3053.67,1486.24 3068.62,1486.24 3071.45,1489.07 3071.44,1618.93 3067.65,1622.73 3002.46,1622.73 2997.92,1618.19 2997.92,1548.17 3000.72,1545.37 3027.57,1545.37 3052.75,1520.18 3052.75,1487.4
+5VA on Top Layer "TOP_LAYER_+5VA_P52845" (solid, remove dead copper, pour order 52845): 632.67,5051.51 624.92,5059.26 624.92,5142.65 631.58,5149.31 691.78,5149.31 696.4,5144.69 696.4,5058 689.92,5051.51
+5VA_TLV3605_1 on Top Layer "TOP_LAYER_+5VA_TLV3605_1_P52841" (solid, remove dead copper, pour order 52841): 17 vertices, not listed, extent 2997.92,2632.5 3069.62,2771.16
+5VA_LMH6518_1 on Top Layer "TOP_LAYER_+5VA_LMH6518_1_P52844" (solid, remove dead copper, pour order 52844): 1177.42,1896.02 1169.56,1888.16 1169.19,1888.16 1169.19,1818.09 1173.89,1813.39 1245.95,1813.39 1250.77,1818.21 1250.77,1889.93 1244.68,1896.02
+5VA_LMH6518_2 on Top Layer "TOP_LAYER_+5VA_LMH6518_2_P52843" (solid, remove dead copper, pour order 52843): 1175.26,748.79 1167.4,740.93 1167.03,740.93 1167.03,670.86 1171.73,666.16 1243.79,666.16 1248.61,670.98 1248.61,742.7 1242.52,748.79
-3.3VA_BUF802_2 on Top Layer "TOP_LAYER_-3.3VA_BUF802_2_P52842" (solid, remove dead copper, pour order 52842): 427.99,934.74 426.35,933.1 426.35,904.08 419.02,896.75 411.5,896.75 410.15,895.4 410.15,864.99 426.11,849.03 478.7,849.03 498.51,868.83 498.51,930.5 494.28,934.74
-3.3VA_BUF802_1 on Top Layer "TOP_LAYER_-3.3VA_BUF802_1_P52840" (solid, remove dead copper, pour order 52840): 427.99,2080.99 426.35,2079.36 426.35,2050.34 419.02,2043 411.49,2043 410.15,2041.65 410.15,2011.25 419.51,2001.89 485.31,2001.89 498.51,2015.09 498.51,2076.76 494.28,2080.99
VBUS on Top Layer "TOP_LAYER_VBUS_P52839" (solid, remove dead copper, pour order 52839): 2737.34,3636.84 2741.6,3641.09 2741.6,3714.16 2736.53,3719.23 2708.65,3719.23 2704.2,3714.78 2704.2,3641 2708.36,3636.84
NetC117_2 on Top Layer "TOP_LAYER_NETC117_2_P52895" (solid, remove dead copper, pour order 52895): 739.96,4866.14 750.79,4876.96 801.95,4876.96 805.8,4880.81 805.8,4940.89 797.26,4949.43 153.91,4949.43 141.41,4936.94 141.41,4876.1 151.38,4866.14
-3.3VA on Top Layer "TOP_LAYER_-3.3VA_P52885" (solid, remove dead copper, pour order 52885): 24 vertices, not listed, extent 1305.69,4570.9 1520,4788.07
+12VA on Top Layer "TOP_LAYER_+12VA_P52875" (solid, remove dead copper, pour order 52875): 18 vertices, not listed, extent 1587.56,4872.41 1797.02,5027.12
+8VA on Top Layer "TOP_LAYER_+8VA_P52891" (solid, remove dead copper, pour order 52891): 18 vertices, not listed, extent 1588.76,4573.83 1802.49,4787.74
+12VA on Top Layer "TOP_LAYER_+12VA_P52881" (solid, remove dead copper, pour order 52881): 1503.16,5767.43 1515.72,5754.88 1515.72,5649.53 1545.82,5619.42 1627.29,5619.42 1635.34,5611.36 1635.34,5542.28 1629.52,5536.46 1460.64,5536.46 1448.9,5548.2 1448.9,5759.61 1456.72,5767.43
+2.5VA on Top Layer "TOP_LAYER_+2.5VA_P52883" (solid, remove dead copper, pour order 52883): 2351.55,4988.67 2352.54,4987.69 2352.54,4907.85 2328.74,4884.05 2328.74,4791.1 2318.68,4781.04 2197.83,4781.04 2190.1,4788.76 2190.1,4948.74 2195.32,4953.95 2308.32,4953.95 2323.88,4969.51 2323.88,4983.81 2328.74,4988.67
NetC122_2 on Top Layer "TOP_LAYER_NETC122_2_P52855" (solid, remove dead copper, pour order 52855): 23 vertices, not listed, extent 2746.22,5075.06 2858.05,5309.32
-3V_INN_TPS7A39 on Top Layer "TOP_LAYER_-3V_INN_TPS7A39_P52888" (solid, remove dead copper, pour order 52888): 2729.7,5252.79 2731.89,5250.6 2731.89,5205.43 2726.5,5200.05 2618.42,5200.05 2581.62,5163.25 2581.62,5078.97 2560.6,5057.95 2446.3,5057.95 2438.08,5066.18 2438.08,5097.71 2496.81,5156.45 2496.81,5246.47 2503.13,5252.79
+3V_INP_TPS7A39 on Top Layer "TOP_LAYER_+3V_INP_TPS7A39_P52892" (solid, remove dead copper, pour order 52892): 2475.27,4987.91 2565.29,4897.89 2677.35,4897.89 2679.9,4895.35 2679.9,4778.62 2672.11,4770.83 2477.14,4770.83 2467.61,4780.37 2467.61,4909.25 2438.18,4938.68 2438.18,5006.39 2440.48,5008.69 2470.49,5008.69 2475.27,5003.91
NetC121_1 on Top Layer "TOP_LAYER_NETC121_1_P52856" (solid, remove dead copper, pour order 52856): 23 vertices, not listed, extent 2686.31,4858.59 2795.91,5023.01
+3P3VD on Top Layer "TOP_LAYER_+3P3VD_P52867" (solid, remove dead copper, pour order 52867): 17 vertices, not listed, extent 3414.73,4769.51 3587.97,4918.43
LM27762_IN on Top Layer "TOP_LAYER_LM27762_IN_P52890" (solid, remove dead copper, pour order 52890): 2948.61,5427.77 2943.21,5422.36 2943.21,5322.95 2951.93,5314.23 3219.78,5314.23 3226.02,5320.47 3226.02,5425.83 3217.56,5434.29 2998.61,5434.29 2992.09,5427.77
+12VA on Top Layer "TOP_LAYER_+12VA_P52863" (solid, remove dead copper, pour order 52863): 2342.6,5626.13 2354.48,5614.25 2382.31,5614.25 2407.63,5588.93 2407.63,5561.1 2427.36,5541.37 2427.36,5519.12 2432.29,5516.15 2456.79,5516.15 2459.33,5518.69 2459.33,5689 2448.02,5700.31 2351.2,5700.31 2342.6,5691.7
-5.5V_IN_TPS7A33 on Top Layer "TOP_LAYER_-5.5V_IN_TPS7A33_P52899" (solid, remove dead copper, pour order 52899): 27 vertices, not listed, extent 376.6,4644.2 1055.28,5011.65
-5VA on Top Layer "TOP_LAYER_-5VA_P52876" (solid, remove dead copper, pour order 52876): 20 vertices, not listed, extent 942.58,4632.47 1068.12,4846.72
TPS62913_IBB_IN on Top Layer "TOP_LAYER_TPS62913_IBB_IN_P52847" (solid, remove dead copper, pour order 52847): 63.85,4832.22 71.72,4840.1 97.73,4840.1 98.64,4839.19 98.64,4814.09 89.96,4805.41 9.45,4805.41 1.8,4797.75 1.8,4750.34 -7.82,4740.72 -46.26,4740.72 -53.54,4748.01 -53.54,4824.56 -45.87,4832.22
TPS62913_IBB_IN on Top Layer "TOP_LAYER_TPS62913_IBB_IN_P52886" (solid, remove dead copper, pour order 52886): 17 vertices, not listed, extent -13.61,4870.85 117.62,5159.15
TPS62913_IBB_IN on Top Layer "TOP_LAYER_TPS62913_IBB_IN_P52887" (solid, remove dead copper, pour order 52887): 814.15,5226.19 490.67,5226.19 484.42,5219.94 484.42,5176.22 492.05,5168.58 882.35,5168.58 882.36,5168.59 887.35,5173.58 887.35,5313.69 884.15,5316.89 829.45,5316.89 826.26,5313.69 826.26,5238.3
NetC123_1 on Top Layer "TOP_LAYER_NETC123_1_P52902" (solid, remove dead copper, pour order 52902): 29 vertices, not listed, extent -234.99,4093.09 288.21,4530.7
NetC134_1 on Top Layer "TOP_LAYER_NETC134_1_P52898" (solid, remove dead copper, pour order 52898): 26 vertices, not listed, extent -78.44,3625.29 389.58,3961.5
+3P3VD_LMH6518_1 on Bottom Layer "BOTTOM_LAYER_+3P3VD_LMH6518_1_P52955" (solid, remove dead copper, pour order 52955): 924.54,1805.22 977.71,1805.22 986.65,1814.16 986.65,1956.44 977.4,1965.69 934.44,1965.69 915.32,1946.57 915.32,1814.43
GND on Bottom Layer "Top Layer-GND" (solid, remove dead copper, pour order 52980): -300,6100 -300,-300 3800,-300 3800,6100 3796.44,6100
+2.5VA_1 on Bottom Layer "BOTTOM_LAYER_+2.5VA_1_P52962" (solid, remove dead copper, pour order 52962): 634.48,2800.81 634.48,2694.29 643.43,2685.34 747.87,2685.34 765.04,2702.52 765.04,2779.53 734,2810.57 644.25,2810.57
-2.5VA on Bottom Layer "BOTTOM_LAYER_-2.5VA_P52978" (solid, remove dead copper, pour order 52978): 207.18,2932.25 243.49,2968.56 480.1,2968.56 483.07,2965.59 483.07,2895.12 478.59,2890.65 422.42,2890.65 387.05,2855.27 216.3,2855.27 55.86,2694.82 -131.09,2694.82 -153.47,2717.76 -153.47,2913.37 -134.59,2932.25
+3P3VD on Bottom Layer "BOTTOM_LAYER_+3P3VD_P52979" (solid, remove dead copper, pour order 52979): 44 vertices, not listed, extent 385.48,1747.74 1984.5,3853.31
+8VA_BUF802_2 on Bottom Layer "BOTTOM_LAYER_+8VA_BUF802_2_P52977" (solid, remove dead copper, pour order 52977): 25 vertices, not listed, extent 66.14,947.37 604.65,1237.28
+2.5VA_1 on Bottom Layer "BOTTOM_LAYER_+2.5VA_1_P52973" (solid, remove dead copper, pour order 52973): 520.05,2685.74 610.62,2685.74 622.55,2673.81 622.55,2636.53 630.97,2628.1 630.97,2522.85 614.58,2507.19 437.68,2507.19 423.24,2521.63 423.24,2655.26 427.62,2659.64 493.95,2659.64
+5VA on Bottom Layer "BOTTOM_LAYER_+5VA_P52976" (solid, remove dead copper, pour order 52976): -65.62,3438.34 147.46,3438.34 155.95,3429.85 155.95,3249.53 134.64,3228.22 2.36,3228.22 -9.17,3239.75 -9.17,3259.18 -29.17,3279.19 -69.77,3279.19 -82.79,3292.2 -82.79,3421.17
-3.3VA_BUF802_1 on Bottom Layer "BOTTOM_LAYER_-3.3VA_BUF802_1_P52975" (solid, remove dead copper, pour order 52975): 25 vertices, not listed, extent 327.43,1842.97 616.93,2298.49
GND on Bottom Layer "BOTTOM_LAYER_GND_P52974" (solid, remove dead copper, pour order 52974): 409.12,3084.29 417.63,3092.8 577.07,3092.8 603.22,3066.66 603.22,2987.41 599.43,2983.63 285.81,2983.63 236.72,3032.71 236.72,3144.8 240.11,3148.19 266.99,3148.19 274.3,3140.88 274.3,3101.76 291.78,3084.29
+2.5VA_1 on Bottom Layer "BOTTOM_LAYER_+2.5VA_1_P52972" (solid, remove dead copper, pour order 52972): 1699.71,2858.49 1666.25,2858.49 1660.17,2864.13 1650.21,2874.53 1592.2,2874.53 1585.78,2868.11 1585.78,2749.59 1612.6,2722.76 1787.22,2722.76 1794.06,2729.6 1794.06,2893.92 1781.19,2906.79 1748.01,2906.79
-2.5VA_1 on Bottom Layer "BOTTOM_LAYER_-2.5VA_1_P52971" (solid, remove dead copper, pour order 52971): 1579.68,3097.6 1579.68,2994.23 1584.71,2989.2 1658.78,2989.2 1667.08,2997.51 1700.21,2997.51 1726.41,2971.31 1726.41,2945.83 1731.72,2940.53 1786.85,2940.53 1789.48,2943.16 1789.48,3105.89 1782.28,3113.09 1595.18,3113.09
-2.5VA_1 on Bottom Layer "BOTTOM_LAYER_-2.5VA_1_P52970" (solid, remove dead copper, pour order 52970): 19 vertices, not listed, extent 427.96,2800.04 644.56,2967.75
-3.3VA_BUF802_2 on Bottom Layer "BOTTOM_LAYER_-3.3VA_BUF802_2_P52969" (solid, remove dead copper, pour order 52969): 22 vertices, not listed, extent 327.43,696.72 546.64,942.97
VA2P5V_DACREFEXT1 on Bottom Layer "BOTTOM_LAYER_VA2P5V_DACREFEXT1_P52968" (solid, remove dead copper, pour order 52968): 19 vertices, not listed, extent 300.78,3099.42 570.45,3253.24
VA5V_DAC on Bottom Layer "BOTTOM_LAYER_VA5V_DAC_P52967" (solid, remove dead copper, pour order 52967): 94.66,3530.07 94.66,3459.47 99.73,3454.4 241.93,3454.4 245.94,3458.41 340.17,3458.41 356.91,3475.15 392.21,3475.15 393.62,3476.55 393.62,3483.09 391.95,3484.76 357.84,3484.76 305,3537.6 102.19,3537.6
+5VA_REF7025_1 on Bottom Layer "BOTTOM_LAYER_+5VA_REF7025_1_P52966" (solid, remove dead copper, pour order 52966): -24.28,3251.78 -24.28,3203.67 -7.76,3187.15 196.01,3187.15 202.51,3180.65 202.51,3149.12 195.83,3142.44 -1,3142.44 -13.68,3129.77 -87.17,3129.77 -92.34,3134.83 -92.34,3243.03 -72.98,3262.39 -34.89,3262.39
+5VA_C on Bottom Layer "BOTTOM_LAYER_+5VA_C_P52965" (solid, remove dead copper, pour order 52965): 2466.18,1465.21 2473.78,1472.81 2539.73,1472.81 2542.37,1475.44 2542.37,1549.93 2530.82,1561.47 2455.37,1561.47 2449.43,1567.41 2449.43,1633.42 2440.44,1642.41 2401.33,1642.41 2395.05,1636.13 2395.05,1470.38 2400.22,1465.21
2.5V_DACREF on Bottom Layer "BOTTOM_LAYER_2.5V_DACREF_P52964" (solid, remove dead copper, pour order 52964): 432.31,3359.94 460.15,3387.78 460.15,3423.32 461.76,3424.92 466.61,3424.92 475.82,3415.72 488.13,3415.72 493.57,3410.28 493.57,3190.72 486.91,3184.06 412.89,3184.06 409.62,3187.32 409.62,3330.38 432.31,3353.06
V3P3V_DAC on Bottom Layer "BOTTOM_LAYER_V3P3V_DAC_P52963" (solid, remove dead copper, pour order 52963): 556.77,3461.59 540.14,3444.96 480.34,3444.96 478.34,3442.96 478.34,3432.45 479.99,3430.79 497.36,3430.79 519.03,3409.12 774.13,3409.12 780.74,3415.73 780.75,3467.68 775.23,3473.19 646.96,3473.19 635.37,3461.59
+8VA_BUF802_1 on Bottom Layer "BOTTOM_LAYER_+8VA_BUF802_1_P52961" (solid, remove dead copper, pour order 52961): 218.51,2203.18 89.54,2203.18 66.96,2180.6 66.96,2152.53 116.21,2103.28 226.1,2103.28 230.25,2107.22 230.25,2191.43
+5VA_OPA140_1 on Bottom Layer "BOTTOM_LAYER_+5VA_OPA140_1_P52960" (solid, remove dead copper, pour order 52960): 597.95,1888.23 587.08,1877.36 587.08,1810.93 603.32,1794.7 725.11,1794.7 739.7,1809.29 739.7,1873.38 724.85,1888.23
+5VA_C on Bottom Layer "BOTTOM_LAYER_+5VA_C_P52959" (solid, remove dead copper, pour order 52959): 2478.73,2611.46 2486.33,2619.06 2539.74,2619.06 2542.37,2621.7 2542.37,2696.18 2530.82,2707.73 2416.35,2707.73 2395.05,2686.43 2395.05,2616.63 2400.22,2611.46
+5VA_OPA140_2 on Bottom Layer "BOTTOM_LAYER_+5VA_OPA140_2_P52958" (solid, remove dead copper, pour order 52958): 597.95,741.98 587.08,731.11 587.08,660.17 605.89,641.37 702.79,641.37 716.2,654.78 716.2,728.07 702.29,741.98
+3P3VD_LMH6518_2 on Bottom Layer "BOTTOM_LAYER_+3P3VD_LMH6518_2_P52957" (solid, remove dead copper, pour order 52957): 929.34,658.96 992.9,658.96 999.35,665.42 999.35,810.06 989.99,819.43 934.44,819.43 919.83,804.82 919.83,668.47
